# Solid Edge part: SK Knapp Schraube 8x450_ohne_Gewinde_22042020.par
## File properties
Author: fknapp
Template: Normal.par
Last saved by: fknapp
Revision: 35
Application: Solid Edge
Username: fknapp
Genauigkeit: 0,99
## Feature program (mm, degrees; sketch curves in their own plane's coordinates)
sketch for "unnamed RevolvedProtrusion 1" plane through (0, 0, 0) normal (1, 0, 0) x-axis (0, 1, 0)
  line (0, 49.2048) -> (7.5, 49.2048)
  arc centre (7.5, 48.7048) radius 0.5 from (7.5, 49.2048) to (7.9949, 48.7762) cw
  line (4, 44.7814) -> (7.9949, 48.7762)
  line (4, 44.7814) -> (4, 39.7814)
  line (4, 39.7814) -> (3, 37.6369)
  line (3, 37.6369) -> (3, 36.5914)
  line (3, 36.5914) -> (4, 36.5914)
  line (4, 36.5914) -> (4, -387.3788)
  line (0, -400.7952) -> (4, -387.3788)
revolve "unnamed RevolvedProtrusion 1" add full turn 360 deg about sketch line (0, 49.2048) -> (0, -400.7952)
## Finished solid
Body 1: solid body, 9 faces, 8 edges, 1 vertex.
  Faces by surface: cone 3, cylinder 3, plane 2, torus 1
  Edges by curve: circle 8
Bounding box of the edges (mm; curved faces can reach further): 15.990 x 15.990 x 436.584, from (-7.9949, -7.9949, -387.3788) to (7.9949, 7.9949, 49.2048).
Cylindrical faces by radius (mm): R3 x1, R4 x2
Conical faces (half-angle, radius in mm at the cone's reference point): 16.6015 deg R4 x1, 25 deg R4 x1, 45 deg R7.9949 x1
Toroidal faces (ring radius, tube radius in mm): R7.5 r0.5 x1
Planar faces by outward normal: +z 2
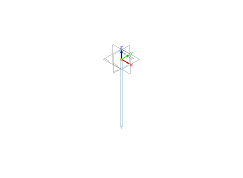
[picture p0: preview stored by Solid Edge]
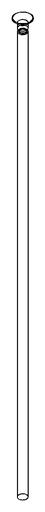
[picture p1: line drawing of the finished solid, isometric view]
